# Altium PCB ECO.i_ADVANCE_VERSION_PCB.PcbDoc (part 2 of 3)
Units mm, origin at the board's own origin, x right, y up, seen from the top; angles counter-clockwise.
Board outline 291.08 x 101.6 mm, 4 copper layers (Top Layer, Layer 1, Layer 2, Bottom Layer), stack 1.161 mm thick; 272 components, 228 nets, 849 pads, 240 vias.
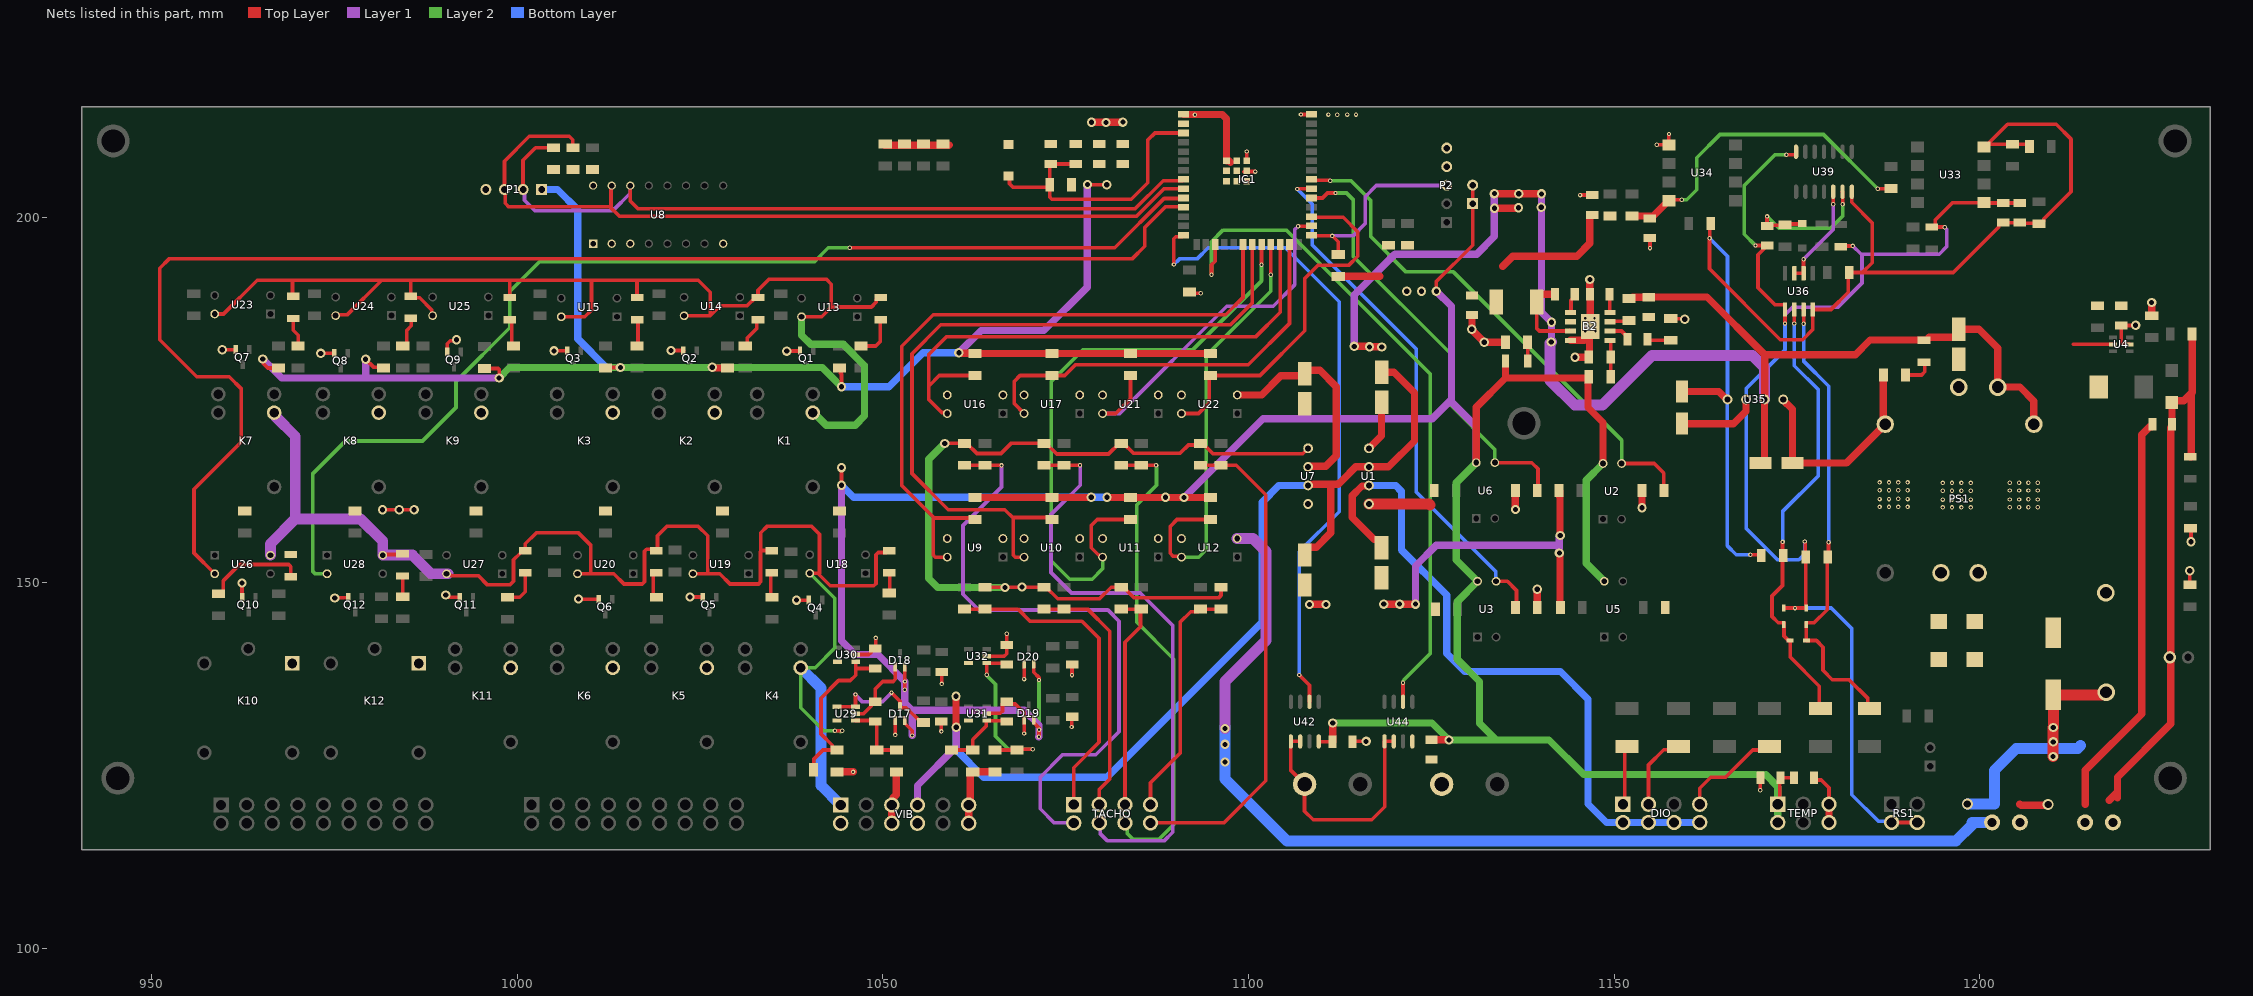
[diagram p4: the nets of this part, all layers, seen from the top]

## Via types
v1: diameter 0.6, hole 0.3, Top Layer to Bottom Layer, 154 vias
v2: diameter 1.27, hole 0.711, Top Layer to Bottom Layer, 80 vias
v3: diameter 2.4, hole 1.6, Top Layer to Bottom Layer, 4 vias
v4: diameter 1.5, hole 1, Top Layer to Bottom Layer, 2 vias

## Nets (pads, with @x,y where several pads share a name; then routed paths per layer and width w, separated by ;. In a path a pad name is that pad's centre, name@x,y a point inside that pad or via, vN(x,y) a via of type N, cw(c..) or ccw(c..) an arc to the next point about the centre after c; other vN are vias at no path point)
+3.3V: C9.2 C12.1 C13.1 C27.1 C28.1 C32.2 C33.2 C35.1 C36.1 D2.POS D17.2 D18.2 D19.2 D20.2 IC1.2 L1.1 P1.1 P4.1 P4.2 R3.2 R4.2 R12.2 R17.1 R18.2 R19.2 R22.1 R23.1 R26.2 R29.2 R30.1 R31.1 R32.2 R43.1 R44.1 R47.2 R48.2 R49.2 R58.1 R59.1 R62.2 R63.2 R64.2 R71.1 R72.2 R73.2 R74.2 R102.1 R103.2 R106.2 R117.2 TEMP.1 TEMP.2 U2.4 U3.4 U5.4 U6.4 U8.16 U34.8 U42.4 U44.4 | length 726.5
  Top Layer w0.5: v2(965.199,180.631) 965.199,180.087 965.894,179.392 R62.2@967.361,179.392 ; v2(979.265,180.602) 980.352,179.515 981.586,179.515 R63.2@981.709,179.392 ; v2(981.583,160.02) v2(983.869,160.02) v2(985.901,160.02) ; R64.2@995.521,179.342 995.529,179.334 997.382,179.334 997.522,179.194 v2(997.522,178.031) ; R32.2@1012.056,179.392 1012.122,179.458 v2(1014.101,179.458) ; R26.2@1044.069,179.392 1044.337,179.125 1044.337,179.09 1044.451,178.976 1044.157,178.681 1044.332,178.505 v2(1044.332,176.82) ; v2(1044.332,163.358) v2(1044.332,165.771) ; v1(1052.981,135.403) 1052.992,135.414 1052.992,136.517 v1(1053.002,136.528) ; D17.2@1052.997,131.191 1052.997,130.826 1054.02,129.804 v1(1054.02,129.136) ; D18.2@1052.997,138.474 1052.997,136.533 v1@1053.008,136.523 ; D19.2@1070.611,131.267 1070.611,130.902 1071.336,130.176 1071.336,129.952 v1(1071.356,129.933) 1071.344,129.921 1071.344,128.987 v1(1071.332,128.975) ; D20.2@1070.611,138.95 1070.611,137.794 1071.346,137.059 v1(1071.346,136.736) ; v2(1077.976,204.47) 1080.58,204.47 v2(1080.601,204.449) ; U42.4@1109.637,128.298 C33.2@1111.449,128.298 ; v2(1125.684,189.891) 1125.684,191.218 1130.646,196.18 P4.1@1130.646,201.86 P4.2@1130.646,204.4 ; U34.8@1157.474,202.272 1157.545,202.343 1157.588,202.3 1157.674,202.386 v1(1159.245,202.386) ; TEMP.1@1172.366,119.747 1172.626,120.007 1172.626,123.259 C36.1@1172.711,123.344 C35.1@1174.608,123.344 ; v1(1186.043,203.911) 1187.836,203.911 R102.1@1187.872,203.947
  Top Layer w1: v2(1026.667,179.488) 1026.74,179.488 1026.836,179.392 R29.2@1028.762,179.392 ; v2(1060.388,181.469) 1060.44,181.418 1062.557,181.418 R43.1@1062.611,181.363 R44.1@1073.117,181.363 R58.1@1083.852,181.363 R59.1@1094.776,181.363 ; R22.1@1062.611,161.678 R23.1@1073.117,161.678 v2@1078.495,161.678 ; v2@1080.654,161.678 R30.1@1083.852,161.678 v2@1091.177,161.678 ; v2(1088.655,161.707) 1088.673,161.689 1091.166,161.689 v2@1091.177,161.678 ; v2(1091.184,161.671) v2@1091.177,161.678 ; R31.1@1094.776,161.678 v2@1091.177,161.678 ; C33.2@1111.449,128.298 C33.2@1111.487,128.26 1111.501,128.273 1111.501,130.824 v2(1111.514,130.837) ; R117.2@1112.266,191.921 1117.957,191.921 1117.981,191.897 ; C32.2@1125.014,128.56 1125.034,128.54 1127.349,128.54 1127.369,128.56 v2(1127.409,128.52) ; U6.4@1131.138,166.448 1131.138,174.027 1135.141,178.03 ; 1134.743,193.288 1136.146,194.691 1144.905,194.691 1146.667,196.453 1146.667,200.284 1146.717,200.334 C28.1@1147.017,200.334 ; D2.POS@1135.141,180.349 1135.141,178.03 ; R12.2@1146.429,178.03 1135.141,178.03 ; R12.2@1146.524,178.192 1146.429,178.098 1146.429,173.99 1148.471,171.948 U2.4@1148.471,166.342 ; R103.2@1152.455,200.184 C27.1@1155.258,200.184 ; C27.1@1154.884,199.854 1155.184,199.854 1155.234,199.904 1155.234,200.067 1157.084,201.917 1157.084,202.01 1157.346,202.272 U34.8@1157.474,202.272
  Layer 1 w1: v2(965.199,180.631) 967.799,178.031 v2(997.522,178.031) ; 979.265,178.181 v2(979.265,180.602) ; v2(1044.332,163.358) 1044.332,142.102 1046.226,140.208 1049.322,140.208 1053.008,136.523 1053.008,135.429 v1(1052.981,135.403) 1052.981,133.58 1053.973,132.588 ; v1(1054.02,129.136) 1054.02,132.541 1053.973,132.588 ; v2(1060.388,181.469) 1063.45,184.531 1072.007,184.531 1077.924,190.448 1077.924,204.418 v2(1077.976,204.47) ; v1(1071.332,128.975) 1071.356,128.999 v1(1071.356,129.933) 1071.356,130.572 1069.34,132.588 1053.973,132.588 ; v2(1091.184,161.671) 1101.979,172.466 1125.12,172.466 1127.583,174.929 ; v2(1125.684,189.891) 1127.76,187.815 1127.76,175.106 1127.583,174.929 ; U6.4@1131.138,166.448 1131.138,171.374 1127.583,174.929
  Layer 2 w0.5: v1(1071.332,128.975) 1071.344,128.987 1071.344,129.921 v1(1071.356,129.933) 1071.351,129.938 1071.351,136.731 v1(1071.346,136.736) ; v1(1159.245,202.386) 1159.904,202.386 1161.288,203.77 1161.288,208.153 1164.463,211.328 1178.626,211.328 v1(1186.043,203.911)
  Layer 2 w1: v2(997.522,178.031) 998.943,179.451 1014.094,179.451 v2(1014.101,179.458) ; v2(1026.667,179.488) 1026.652,179.473 1014.116,179.473 v2(1014.101,179.458) ; v2(1044.332,176.82) 1041.694,179.458 v2(1014.101,179.458) ; v2(1111.514,130.837) 1125.092,130.837 v2(1127.409,128.52) ; v2@1127.413,128.524 1133.861,128.524 ; U6.4@1131.138,166.448 1128.395,163.705 1128.395,153.139 U3.4@1131.311,150.224 1128.522,147.435 1128.522,139.573 1131.575,136.52 1131.575,130.81 1133.861,128.524 ; U2.4@1148.433,166.38 U2.4@1148.471,166.342 1146.175,164.045 1146.175,152.693 U5.4@1148.644,150.224 ; TEMP.2@1172.366,117.248 TEMP.1@1172.366,119.747 1172.366,122.145 1170.712,123.799 1145.82,123.799 1141.095,128.524 1133.861,128.524
  Bottom Layer w1: P1.1@1003.336,203.802 1005.492,203.802 1008.253,201.041 1008.253,183.388 1012.183,179.458 v2(1014.101,179.458) ; v2(1044.332,163.358) 1045.983,161.707 1062.573,161.707 v2(1078.495,161.707) v2(1080.654,161.707) ; v2(1044.332,176.82) 1050.834,176.82 1055.483,181.469 v2(1060.388,181.469)
  other v2: 1121.62,189.891 1123.652,189.891
+5_RS: C26.1 C29.1 C30.1 R101.2 R104.2 R105.1 R108.1 R109.1 R110.1 U33.8 U35.4 U36.8 U39.14 | length 166.2
  Top Layer w0.5: v1@1163.026,197.142 1163.026,192.953 1172.718,183.261 1175.766,183.261 1177.163,184.658 U36.8@1177.163,187.395 1179.646,187.395 1181.989,189.738 1181.989,192.295 R108.1@1182.136,192.442 1183.931,192.442 ; v1(1163.05,197.142) 1163.05,198.842 R105.1@1163.09,198.882 ; v1(1168.626,153.866) 1169.945,153.866 1170.009,153.93 1170.015,153.924 R110.1@1170.09,153.849 ; U39.14@1182.49,203.497 1182.475,203.483 1182.475,202.047 1185.291,199.231 1185.291,193.802 1183.931,192.442 ; U33.8@1200.571,209.629 1200.699,209.629 U33.8@1201.047,209.977 ; R104.2@1206.776,209.677 1206.476,209.977 R101.2@1204.472,209.977 U33.8@1201.047,209.977 ; 1183.931,192.442 1196.377,192.442 1202.598,198.663 1202.598,198.963 1202.898,199.263 C26.1@1203.198,199.263 C29.1@1205.452,199.263 1205.527,199.188 1208.024,199.188 R109.1@1208.099,199.113 1208.399,199.113 1208.749,199.463 1208.749,199.763 1212.469,203.483 1212.469,210.693 1210.437,212.725 1203.795,212.725 U33.8@1201.047,209.977
  Top Layer w1: C30.1@1159.277,176.182 1164.314,176.182 1165.402,175.093 U35.4@1165.497,175.093
  Bottom Layer w0.5: v1@1163.026,197.142 1165.497,194.672 U35.4@1165.497,175.093 1165.479,175.075 1165.479,155.067 1166.68,153.866 v1(1168.626,153.866)
+5V: B2.2 C2.1 C4.1 C6.1 C10.1 C24.1 C31.1 D1.POS D5.POS D6.POS D7.POS D8.POS D9.POS D10.POS D11.POS D12.POS D13.POS D14.POS D15.POS D16.POS K1.2 K2.2 K3.2 K4.2 K5.2 K6.2 K7.2 K8.2 K9.2 K10.A1 K11.2 K12.A1 L2.2 PS1.3 R9.1 R98.2 U1.2 U4.5 U7.2 U13.4 U14.4 U15.4 U18.4 U19.4 U20.4 U23.4 U24.4 U25.4 U26.4 U27.4 U28.4 U29.5 U30.5 U31.5 U32.5 U35.2 VIB.1 VIB.2 VIB.7 VIB.8 | length 724.1
  Top Layer w0.5: U23.4@958.628,186.778 959.827,186.778 964.444,191.395 969.264,191.395 ; D11.POS@969.377,189.183 969.264,189.296 969.264,191.395 ; U24.4@974.884,186.651 976.718,186.651 981.456,191.389 ; U28.4@981.609,153.797 981.697,153.885 984.225,153.885 D16.POS@984.312,153.972 ; U25.4@988.426,186.553 988.301,186.677 988.301,187.338 986.65,188.988 985.651,188.988 D12.POS@985.435,189.204 985.435,191.22 985.387,191.268 ; U27.4@990.339,151.257 990.473,151.123 990.861,151.123 990.982,151.003 994.664,151.003 995.934,149.733 998.982,149.733 999.49,150.241 999.49,153.162 1000.469,154.141 1000.469,154.157 1000.724,154.412 D15.POS@1001.084,154.412 1001.112,154.44 1001.112,155.374 1002.583,156.845 1008.38,156.845 1010.031,155.194 1010.031,151.257 ; D13.POS@998.962,189.033 998.962,191.389 ; U15.4@1006.018,186.403 1009.236,186.403 1010.158,187.325 1010.158,191.262 1010.285,191.389 ; U20.4@1008.246,151.257 1010.031,151.257 ; D7.POS@1016.426,189.033 1016.378,189.081 1016.378,191.389 ; D10.POS@1018.585,154.412 1018.383,154.614 1017.69,154.614 1017.397,154.321 1017.397,150.153 1017.104,149.86 1014.603,149.86 1013.206,151.257 1010.031,151.257 ; D10.POS@1018.994,154.418 1019.175,154.599 1019.175,156.464 1020.445,157.734 1024.763,157.734 1026.033,156.464 1026.033,151.257 ; U14.4@1022.819,186.533 1026.384,186.533 ; U19.4@1024.02,151.257 1026.033,151.257 ; D9.POS@1034.796,154.418 1034.782,154.432 1033.438,154.432 1033.291,154.286 ; U13.4@1038.879,186.403 1041.621,186.403 1042.953,187.735 ; U18.4@1040.005,151.318 1041.285,151.318 ; v1(1043.432,129.794) v1(1044.448,129.794) ; D5.POS@1049.724,189.033 1049.364,189.033 1049.109,188.778 1049.109,188.418 1048.427,187.735 1042.953,187.735 ; D8.POS@1050.715,154.418 1050.46,154.163 1049.348,154.163 1049.055,153.87 1049.055,149.899 1048.762,149.606 1042.797,149.606 1041.285,151.118 1041.285,151.318 ; 1212.768,182.626 1216.057,182.626 U4.5@1218.189,182.626 ; 969.264,191.395 985.26,191.395 985.387,191.268 ; 985.387,191.268 985.266,191.389 998.962,191.389 ; 998.962,191.389 1010.285,191.389 ; 1010.285,191.389 1016.378,191.389 ; 1016.378,191.389 1024.763,191.389 1026.384,189.768 1026.384,186.533 ; 1026.033,151.257 1027.684,151.257 1029.081,149.86 1032.979,149.86 1033.272,150.153 1033.272,154.266 1033.291,154.286 ; 1026.384,186.533 1027.737,187.886 1031.418,187.886 1032.565,189.033 D6.POS@1032.925,189.033 1032.925,190.026 1034.415,191.516 1042.289,191.516 1042.953,190.852 1042.953,187.735 ; 1033.291,154.286 1033.291,156.864 1034.161,157.734 1040.257,157.734 1041.326,156.665 1041.326,151.318 1041.285,151.318
  Top Layer w1: v2(1060.005,134.518) 1060.005,130.292 v2(1060.026,130.271) ; C10.1@1107.449,154.552 1107.449,154.586 1107.749,154.886 1109.291,154.886 1111.25,156.845 1111.25,163.498 ; U7.2@1108.149,163.333 1108.216,163.4 1108.463,163.4 1108.561,163.498 1111.25,163.498 ; 1112.303,163.498 1112.889,164.084 1114.678,165.873 U1.2@1116.463,165.873 1119.135,165.873 1122.68,169.418 1122.68,176.022 1119.895,178.807 1118.481,178.807 1118.181,178.507 C4.1@1118.181,178.384 ; 1112.303,163.613 1112.188,163.498 1111.25,163.498 ; v2(1114.44,182.347) 1116.468,182.347 v2(1116.532,182.282) 1118.175,182.282 v2(1118.201,182.257) ; v2(1133.613,203.236) 1136.922,203.236 v2(1136.935,203.223) 1140.029,203.223 v2(1140.048,203.204) ; v2(1133.641,201.225) 1136.834,201.225 v2(1136.904,201.295) ; R9.1@1152.022,188.891 1152.322,188.891 1152.497,189.066 C6.1@1154.714,189.066 1154.751,189.103 1162.685,189.103 1170.577,181.211 ; C31.1@1169.982,166.389 1170.259,166.389 1170.559,166.689 1170.559,175.075 U35.2@1170.577,175.093 1170.577,181.211 ; PS1.3@1207.383,171.704 1207.383,174.885 1205.484,176.784 v3(1202.436,176.784) 1202.436,182.118 1199.878,184.676 C2.1@1197.102,184.676 1197.102,184.006 1196.677,183.581 1193.097,183.581 1192.727,183.212 D1.POS@1192.367,183.212 1184.988,183.212 1182.987,181.211 1170.577,181.211
  Layer 1 w1: VIB.7@1054.725,119.634 1054.725,122.291 1060.026,127.592 v2(1060.026,130.271) ; v2(1114.44,182.347) 1114.44,189.372 1120.013,194.945 1131.189,194.945 1133.613,197.369 v2(1133.613,203.236) ; v2(1140.048,203.204) 1140.048,187.029 v2(1141.43,185.647) 1141.415,185.631 1141.415,182.964 v2(1141.399,182.949)
  Layer 1 w1.5: U26.4@966.248,153.797 966.248,155.353 969.772,158.877 ; K7.2@966.747,173.284 966.747,173.149 966.997,172.899 966.997,172.701 969.645,170.053 969.645,159.004 969.772,158.877 ; U27.4@990.553,151.257 988.187,151.257 985.647,153.797 U28.4@981.609,153.797 981.609,155.712 978.572,158.75 969.899,158.75 969.772,158.877 ; v2(1141.399,182.949) 1141.227,182.777 1141.227,177.709 1144.607,174.329 1148.419,174.329 1155.192,181.102 1168.908,181.102 1170.577,179.433 U35.2@1170.577,175.093
  Layer 2 w0.5: U18.4@1040.005,151.318 1043.432,147.891 1043.432,141.097 1040.736,138.401 K4.2@1038.771,138.401 1038.771,132.931 1041.908,129.794 v1(1043.432,129.794) 1044.067,129.794 v1@1044.194,129.667
  Layer 2 w1: U13.4@1038.879,186.403 1038.879,183.877 1040.13,182.626 1044.575,182.626 1047.496,179.705 1047.496,172.847 1046.226,171.577 1042.239,171.577 1040.532,173.284 K1.2@1040.411,173.284
  Bottom Layer w1: v2(1060.026,130.271) 1060.026,127.17 1063.752,123.444 1080.643,123.444 1101.852,144.653 1101.852,161.036 1104.149,163.333 U7.2@1108.149,163.333
  Bottom Layer w1.5: K4.2@1038.771,138.401 1041.527,135.645 1041.527,122.332 VIB.1@1044.225,119.634
  other v2: 1140.032,201.377
+5V_DIO: C5.1 R5.2 R6.2 R13.2 R14.2 U1.4 | length 54.9
  Top Layer w1: v2(1118.5,147.102) v2(1120.659,147.102) v2(1122.818,147.102) ; R6.2@1142.47,162.638 1142.57,162.538 1142.57,161.745 1142.591,161.724 v2@1142.591,156.5 ; v2@1142.591,154.087 1142.591,146.694 R14.2@1142.642,146.643
  Top Layer w1.5: U1.4@1116.463,160.793 1124.701,160.793 1124.839,160.655
  Layer 1 w1: v2(1122.818,147.102) 1122.818,152.318 1125.645,155.145 1142.503,155.145 ; v2(1142.503,154.087) 1142.503,155.067 1142.503,156.3 1142.63,156.427 v2(1142.63,156.5)
+5V_FAN: C11.1 R20.1 R21.1 R27.1 R28.1 R41.1 R42.1 R56.1 R57.1 U7.4 | length 120.4
  Top Layer w0.5: v2(1058.462,169.081) R41.1@1061.175,169.081 1061.475,169.081 1062.852,167.704 1066.147,167.704 1067.524,169.081 R42.1@1072.016,169.081 1072.349,169.415 1072.349,169.048 1073.757,167.64 1080.86,167.64 1082.301,169.081 R56.1@1082.601,169.081 1082.901,169.081 1084.252,167.73 1090.639,167.73 1091.78,168.871 1093.219,168.871 R57.1@1093.43,169.081 1093.73,169.081 1095.142,167.669 1107.405,167.669 U7.4@1108.149,168.413 ; R20.1@1063.984,149.423 v2@1066.72,149.423 ; v2(1066.684,149.388) v2@1066.72,149.423 ; v2(1069.025,149.459) v2@1068.99,149.423 ; R28.1@1096.226,149.423 1096.226,148.298 1095.883,147.955 1084.369,147.955 1082.901,149.423 1081.222,149.423 1079.627,147.828 1073.911,147.828 1072.316,149.423 R21.1@1072.016,149.423 v2@1068.99,149.423 ; v2@1066.72,149.423 v2@1068.99,149.423
  Layer 2 w1: v2(1058.462,169.081) 1056.282,166.901 1056.282,150.599 1057.493,149.388 v2(1066.684,149.388)
+12: 12volts.2 C25.1 D21.1 D25.POS P3.1 R99.2 | length 78.5
  Top Layer w1: 1217.678,120.282 1218.577,121.181 ; 1218.819,120.647 1218.819,123.444 1226.116,130.741 1226.116,140.081 1226.116,171.255 1226.285,171.424 1226.285,174.61 D21.1@1226.238,174.657 1226.485,174.905 1227.862,174.905 1228.892,175.935 ; D25.POS@1228.762,167.252 1228.887,167.252 1228.892,167.257 1228.892,175.935 ; R99.2@1229.027,184.019 1229.027,176.07 1228.892,175.935
+48V: C3.1 D3.1 D4.1 PS1.2
  other v1: 1204.087,160.35 1205.365,160.35 1206.643,160.35 1207.921,160.35 1204.087,161.417 1205.365,161.417 1207.921,161.417 1206.643,161.449 1204.087,162.636 1205.365,162.636 1206.643,162.636 1207.921,162.636 1204.087,163.703 1205.365,163.703 1206.643,163.703 1207.921,163.703
  other v3: 1217.242,148.643
AGND: C26.2 C29.2 C30.2 C34.1 D22.NEG D23.NEG R114.2 RS1.2 RS1.4 U33.5 U35.3 U36.5 U37.2 U39.7 U40.1 | length 191
  Top Layer w0.5: v1(1169.323,196.139) 1169.325,196.137 C34.1@1170.446,196.137 ; C34.1@1170.924,196.135 1169.67,194.881 1169.67,190.373 1171.988,188.055 1173.303,188.055 1173.353,188.005 U36.5@1173.353,187.395 1173.354,187.394 1173.354,185.485 v1(1173.356,185.484) ; U37.2@1173.211,146.564 v1(1174.728,146.564) U40.1@1176.245,146.564 1176.24,146.569 1176.24,146.96 1176.192,147.009 1176.192,153.849 1176.117,153.924 1176.117,155.591 1176.069,155.638 v1(1176.069,155.665) ; v1(1173.541,208.562) 1173.553,208.574 1174.826,208.574 1174.87,208.618 U39.7@1174.87,208.965 ; D22.NEG@1180.996,195.996 1181.088,196.088 1181.093,196.083 v1(1182.625,196.083) ; RS1.2@1187.928,117.248 RS1.4@1191.428,117.248 ; D23.NEG@1193.439,198.67 D23.NEG@1193.656,198.67 ; v1(1195.207,198.637) 1195.18,198.637 1195.148,198.67 D23.NEG@1193.656,198.67 ; C29.2@1205.452,201.963 C26.2@1203.198,201.963 1200.617,201.963 U33.5@1200.571,202.009 1196.292,202.009 1193.911,199.628 1193.911,198.925 D23.NEG@1193.656,198.67
  Top Layer w1: C30.2@1159.277,171.782 1166.319,171.782 1168.019,173.482 1168.019,175.075 U35.3@1168.037,175.093
  Layer 1 w0.5: v1(1173.356,185.484) 1173.356,186.693 1174.369,187.706 1180.592,187.706 1183.894,191.008 1183.894,194.814 ; v1(1182.625,196.083) 1183.765,194.943 ; 1183.763,194.945 1194.435,194.945 1195.451,195.961 1195.451,198.367 1195.207,198.61 v1(1195.207,198.637)
  Layer 2 w0.5: v1(1169.323,196.139) 1167.765,197.697 1167.765,204.343 1171.984,208.562 v1@1173.518,208.562
  Bottom Layer w0.5: v1(1173.356,185.484) 1173.356,181.867 1168.037,176.548 U35.3@1168.037,175.093 1168.037,157.462 1172.337,153.162 1175.258,153.162 1176.069,153.973 v1(1176.069,155.665) ; v1(1174.728,146.564) 1179.697,146.564 1182.497,143.764 1182.497,121.031 1186.128,117.4 1187.775,117.4 RS1.2@1187.928,117.248
AIR_CON: DIO.7 F4.1 | length 14.1
  Top Layer w0.5: DIO.7@1161.693,119.747 1161.693,121.944 1163.193,123.444 1165.225,123.444 1168.934,127.153 1170.745,127.153 F4.1@1171.22,127.628
AIR_CON_MCU: IC1.31 R16.2 U6.3 | length 59.6
  Top Layer w0.5: IC1.31@1108.631,202.637 1110.115,202.637 1110.805,203.327 v1(1111.885,203.327) ; U6.3@1133.678,166.448 1138.731,166.448 1139.571,165.608 1139.571,162.719 R16.2@1139.49,162.638
  Layer 2 w0.5: v1(1111.885,203.327) 1113.409,203.327 1114.298,202.438 1114.298,194.691 1127.506,181.483 1127.506,174.421 1133.678,168.25 U6.3@1133.678,166.448
CS: IC1.14 U42.6 | length 89.1
  Top Layer w0.5: v1(1089.787,193.548) 1089.787,197.064 1090.08,197.357 1090.931,197.357 IC1.14@1091.131,197.557 ; v1(1106.932,137.414) 1108.329,136.017 U42.6@1108.329,133.747
  Bottom Layer w0.5: v1(1089.787,193.548) 1090.549,194.31 1092.962,194.31 1094.486,195.834 1105.027,195.834 1112.393,188.468 1112.393,159.749 1106.932,154.288 v1@1106.932,137.581
CS2: IC1.17 U44.6 | length 94
  Top Layer w0.5: v1(1094.94,192.141) 1094.94,193.494 1095.436,193.99 IC1.17@1095.436,196.307 ; v1(1121.123,136.35) 1121.125,136.349 U44.6@1121.125,133.747
  Layer 2 w0.5: v1(1094.94,192.141) 1094.94,196.669 1096.518,198.247 1105.154,198.247 1124.839,178.562 1124.839,140.343 1121.283,136.787 1121.283,136.779 1121.143,136.639 1121.143,136.369 v1(1121.123,136.35)
DGND: C5.2 DIO.2 DIO.4 DIO.6 DIO.8 U1.3 | length 94
  Top Layer w1: U1.3@1116.463,163.333 1116.396,163.266 1115.512,163.266 1114.171,161.925 1114.171,158.955 1117.181,155.945 1117.881,155.945 1118.181,155.645 C5.2@1118.181,154.945
  Bottom Layer w1: U1.3@1116.463,163.333 1120.129,163.333 1120.902,162.56 1120.902,154.559 1127.118,148.343 1127.118,140.342 1129.57,137.89 1142.651,137.89 1146.429,134.112 1146.429,119.761 1148.942,117.248 DIO.2@1151.192,117.248 DIO.4@1154.692,117.248 ; DIO.4@1154.692,117.248 DIO.6@1158.193,117.247 DIO.8@1161.693,117.247
DOOR1_MCU: IC1.32 R8.2 U3.3 | length 72.6
  Top Layer w0.5: v1(1106.658,203.875) 1106.674,203.891 1108.614,203.891 IC1.32@1108.631,203.907 ; U3.3@1133.851,150.224 1135.397,150.224 1136.65,148.971 1136.65,146.803 R8.2@1136.49,146.643
  Bottom Layer w0.5: v1(1106.658,203.875) 1108.71,201.823 1108.71,196.215 1122.934,181.991 1122.934,162.433 1133.793,151.574 1133.793,150.281 U3.3@1133.851,150.224
DOOR_1: DIO.3 F2.1 | length 10.5
  Top Layer w0.5: DIO.3@1154.692,119.747 1154.693,125.104 1156.774,127.185 1158.364,127.185 F2.1@1158.806,127.628
EN: C14.1 C15.1 IC1.3 R71.2 SW1.1 | length 40.4
  Top Layer w0.5: SW1.1@1067.181,205.613 1067.308,205.486 1067.308,204.597 1067.816,204.089 1069.848,204.089 1069.85,204.087 R71.2@1072.458,204.087 ; C14.1@1076.342,207.291 C15.1@1072.933,207.291 1072.808,207.166 R71.2@1072.808,204.461 1072.808,204.437 R71.2@1072.458,204.087 ; IC1.3@1091.131,211.527 1087.192,211.527 1086.231,210.566 1086.231,204.724 1083.973,202.466 1073.101,202.466 1072.808,202.759 1072.808,203.811 1072.532,204.087 R71.2@1072.458,204.087
ENABLE: U36.2 U36.3 U39.12 | length 14
  Top Layer w0.5: U36.3@1174.623,192.335 U36.2@1175.893,192.335 1175.893,194.1 v1@1175.895,194.102 ; U39.12@1179.95,203.497 1179.929,203.477 1179.958,203.449 v1(1179.958,201.796)
  Layer 1 w0.5: v1(1175.896,194.259) 1179.958,198.321 v1(1179.958,201.796)
FAN_1: IC1.20 R22.2 U9.4 | length 94.8
  Top Layer w0.5: 1056.867,158.877 1056.867,153.822 1057.16,153.529 U9.4@1058.801,153.529 ; R22.2@1062.611,158.678 1062.412,158.877 1057.021,158.877 1052.576,163.322 1052.576,182.372 1056.894,186.69 1096.899,186.69 1099.246,189.037 IC1.20@1099.246,196.307
FAN_2: IC1.21 R23.2 U10.4 | length 102.3
  Top Layer w0.5: U10.4@1069.307,153.529 1068.109,153.529 1067.816,153.822 1067.816,158.877 ; R23.2@1073.117,158.678 1072.855,158.94 1067.88,158.94 1067.816,158.877 ; IC1.21@1100.516,196.307 1100.516,188.275 1097.534,185.293 1057.91,185.293 1053.973,181.356 1053.973,164.973 1058.926,160.02 1066.673,160.02 1067.816,158.877
FAN_3: IC1.22 R30.2 U11.4 | length 85
  Top Layer w0.5: U11.4@1080.042,153.529 1079.852,153.529 1079.534,153.847 1079.45,153.847 1078.484,154.813 1078.484,157.861 1079.301,158.678 R30.2@1083.852,158.678 ; v1(1101.765,193.518) 1101.775,193.528 1101.775,196.258 IC1.22@1101.765,196.268
  Layer 2 w0.5: U11.4@1080.042,153.529 1080.042,151.926 1078.611,150.495 1075.563,150.495 1073.023,153.035 1073.023,177.546 1077.341,181.864 1092.327,181.864 1101.765,191.302 v1(1101.765,193.518)
FAN_4: IC1.23 R31.2 U12.4 | length 60.6
  Top Layer w0.5: U12.4@1090.831,153.529 1090.697,153.663 1089.667,153.663 1089.279,154.051 1089.279,157.734 1090.223,158.678 R31.2@1094.776,158.678 ; v1(1103.042,192.131) 1103.049,192.138 1103.049,196.3 IC1.23@1103.056,196.307
  Layer 2 w0.5: U12.4@1090.831,153.529 1093.204,153.529 1094.232,154.557 1094.232,181.102 1103.033,189.903 1103.033,192.123 v1(1103.042,192.131)
FAN_5: IC1.24 R43.2 U16.4 | length 76.2
  Top Layer w0.5: U16.4@1058.801,173.167 1058.667,173.301 1058.034,173.301 1056.259,175.075 1056.259,176.911 ; R43.2@1062.611,178.363 1057.711,178.363 1056.259,176.911 ; IC1.24@1104.326,196.307 1104.326,187.005 1100.963,183.642 1058.672,183.642 1056.259,181.229 1056.259,176.911
FAN_6: IC1.25 R44.2 U17.4 | length 56.7
  Top Layer w0.5: U17.4@1069.307,173.167 1067.943,174.531 1067.943,177.546 1068.76,178.363 R44.2@1073.117,178.363 1074.856,178.363 1076.344,179.851 1099.966,179.851 1105.596,185.481 IC1.25@1105.596,196.307
FAN_7: IC1.28 R58.2 U21.4 | length 51.5
  Top Layer w0.5: U21.4@1080.042,173.167 1081.852,173.167 1083.852,175.167 R58.2@1083.852,178.363 ; v1(1106.781,198.776) 1106.8,198.795 1108.599,198.795 IC1.28@1108.631,198.827
  Layer 1 w0.5: U21.4@1080.042,173.167 1082.36,173.167 1097.026,187.833 1103.376,187.833 1106.297,190.754 1106.297,198.292 v1(1106.781,198.776)
FAN_8: IC1.29 R59.2 U22.4 | length 49.8
  Top Layer w0.5: U22.4@1090.831,173.167 1093.155,173.167 1094.613,174.625 1094.613,178.2 R59.2@1094.776,178.363 1101.574,178.363 1107.694,184.483 1107.694,191.643 1109.472,193.421 1113.663,193.421 1114.933,194.691 1114.933,197.993 1112.935,199.991 1108.736,199.991 IC1.29@1108.631,200.097
FAN_RELAY1: IC1.10 U28.2 | length 155.1
  Top Layer w0.5: v1(1045.464,195.834) 1081.721,195.834 1088.452,202.565 1091.059,202.565 IC1.10@1091.131,202.637
  Layer 2 w0.5: U28.2@973.989,151.257 972.351,151.257 972.058,151.55 972.058,164.973 976.503,169.418 987.044,169.418 991.616,173.99 991.616,177.546 998.982,184.912 998.982,189.865 1003.046,193.929 1040.638,193.929 1042.543,195.834 v1(1045.464,195.834)
FAN_RELAY2: IC1.11 U26.2 | length 197.9
  Top Layer w0.5: U26.2@958.628,151.257 955.802,154.083 955.802,162.814 962.279,169.291 962.279,176.53 960.628,178.181 956.183,178.181 951.103,183.261 951.103,193.04 952.373,194.31 1084.072,194.31 1085.795,196.033 1085.795,198.605 1088.612,201.422 1091.075,201.422 IC1.11@1091.131,201.367
FAN_T1: R20.2 R24.2 TACHO.1 | length 44.2
  Top Layer w0.5: R24.2@1061.175,146.423 R20.2@1063.984,146.423 1068.459,146.423 1070.103,144.779 1077.215,144.779 1079.557,142.437 1079.557,128.2 1076.095,124.738 TACHO.1@1076.095,119.687
FAN_T2: R21.2 R25.2 TACHO.3 | length 34.6
  Top Layer w0.5: R21.2@1072.016,146.423 R25.2@1074.752,146.423 1077.984,146.423 1081.024,143.383 1081.024,123.19 1079.595,121.761 TACHO.3@1079.595,119.687
FAN_T3: R27.2 R33.2 TACHO.5 | length 30.4
  Top Layer w0.5: R27.2@1082.601,146.423 R33.2@1085.337,146.423 1085.215,146.301 1085.215,144.018 1083.096,141.899 TACHO.5@1083.095,119.687
FAN_T4: R28.2 R34.2 TACHO.7 | length 32.9
  Top Layer w0.5: TACHO.7@1086.596,119.687 1086.596,122.666 1090.676,126.746 1090.676,144.653 1092.096,146.073 1093.08,146.073 R34.2@1093.43,146.423 R28.2@1096.226,146.423
FAN_T5: R41.2 R45.2 TACHO.2 | length 85.9
  Top Layer w0.5: R41.2@1061.175,166.081 R45.2@1063.984,166.081 1066.2,166.081 v1@1066.223,166.058
  Layer 1 w0.5: v1@1066.223,166.058 1066.223,163.126 1060.958,157.861 1060.958,148.463 1063.117,146.304 1080.77,146.304 1082.294,144.78 1082.294,129.667 1079.119,126.492 1074.547,126.492 1071.499,123.444 1071.499,119.126 1073.438,117.187 TACHO.2@1076.095,117.187
  other v1: 1066.211,166.07
FAN_T6: R42.2 R46.2 TACHO.4 | length 81.6
  Top Layer w0.5: R42.2@1072.016,166.081 R46.2@1074.752,166.081 v1(1076.95,166.081) v1@1076.992,166.123
  Layer 1 w0.5: v1@1076.992,166.123 1076.992,163.354 1072.993,159.355 1072.993,151.414 1075.786,148.621 1085.184,148.621 1089.632,144.173 1089.632,115.924 1088.433,114.725 1080.726,114.725 1079.702,115.749 1079.702,117.081 TACHO.4@1079.595,117.188
FAN_T7: R56.2 R60.2 TACHO.6 | length 66.3
  Top Layer w0.5: R56.2@1082.601,166.081 R60.2@1085.337,166.081 v1(1087.359,166.081) v1@1087.406,166.035
  Layer 2 w0.5: TACHO.6@1083.095,117.187 1083.402,116.881 1083.402,115.732 1084.199,114.935 1087.755,114.935 1089.787,116.967 1089.787,139.573 1084.707,144.653 1084.707,160.655 1087.406,163.354 v1@1087.406,166.035
FAN_T8: R57.2 R61.2 TACHO.8 | length 67.9
  Top Layer w0.5: TACHO.8@1086.596,117.187 1096.611,117.187 1102.36,122.936 1102.36,162.052 1098.331,166.081 R61.2@1096.226,166.081 R57.2@1093.43,166.081
FGND: C3.2 C11.2 POWER.1 PS1.1 U7.3 U9.2 U10.2 U11.2 U12.2 U16.2 U17.2 U21.2 U22.2 | length 214.8
  Top Layer w1: U22.2@1098.451,175.707 1101.791,175.707 1104.399,178.315 1107.149,178.315 1107.449,178.615 1107.449,179.084 1109.763,179.084 1112.012,176.835 1112.012,167.386 1110.566,165.94 1108.216,165.94 U7.3@1108.149,165.873
  Top Layer w1.5: v2(1210.022,126.258) 1210.03,126.265 v2(1210.03,128.268) 1210.034,128.272 v2(1210.034,130.231) ; v2@1210.056,130.231 C3.2@1210.056,133.838 ; C3.2@1210.056,134.688 1216.662,134.688 1217.012,135.039 v3(1217.256,135.039)
  Layer 1 w1.5: v2(1096.783,130.084) 1096.783,136.536 1102.36,142.113 1102.36,154.305 1100.596,156.069 U12.2@1098.451,156.069
  Bottom Layer w1.5: v2@1096.772,125.512 1096.772,123.19 1105.242,114.72 1196.709,114.72 1198.907,116.918 1198.907,117.248 POWER.1@1201.971,117.248 ; v2@1096.772,130.084 v2@1096.772,130.302 ; v2(1096.783,125.512) v2(1096.783,127.925) v2(1096.783,130.084) ; v4(1198.296,119.775) 1201.943,119.775 1201.971,119.747 1201.971,124.376 1204.976,127.381 1213.387,127.381 1213.747,127.74
FLOOD_SENSOR_NO: DIO.1 F1.1 | length 8.1
  Top Layer w0.5: DIO.1@1151.192,119.747 1151.443,119.998 1151.443,127.334 F1.1@1151.737,127.628
FLOOD_SENSOR_SIG: IC1.33 R7.2 U2.3 | length 72
  Top Layer w0.5: IC1.33@1108.631,205.177 1108.764,205.043 1111.098,205.043 1111.132,205.009 v1(1111.159,205.009) ; U2.3@1151.011,166.342 1155.474,166.342 1156.793,165.023 R7.2@1156.793,162.638
  Layer 2 w0.5: v1(1111.159,205.009) 1114.013,205.009 1116.711,202.311 1116.711,197.358 1121.537,192.532 1128.014,192.532 1151.011,169.535 U2.3@1151.011,166.342
GND: 12volts.1 B2.4 B2.9 C2.2 C4.2 C6.2 C7.2 C9.1 C10.2 C12.2 C13.2 C14.2 C15.2 C16.2 C17.2 C18.2 C19.2 C20.2 C21.2 C22.2 C23.2 C24.2 C25.2 C27.2 C28.2 C31.2 C32.1 C33.1 C35.2 C36.2 D17.1 D18.1 D19.1 D20.1 IC1.1 IC1.40 IC1.41 IC1.42 IC1.43 IC1.44 IC1.45 IC1.46 IC1.47 IC1.48 IC1.49 P1.4 P2.4 P2.5 PS1.5 Q1.2 Q2.2 Q3.2 Q4.2 Q5.2 Q6.2 Q7.2 Q8.2 Q9.2 Q10.2 Q11.2 Q12.2 R1.2 R2.2 R7.1 R8.1 R10.1 R11.1 R15.1 R16.1 R85.1 R86.1 R88.1 R92.1 R93.2 R94.1 R95.1 R96.1 R97.1 R100.1 R115.1 R116.2 SW1.2 TEMP.5 TEMP.6 U1.1 U4.2 U7.1 U8.1 U8.2 U8.3 U8.8 U9.3 U10.3 U11.3 U12.3 U16.3 U17.3 U21.3 U22.3 U29.2 U30.2 U31.2 U32.2 U34.5 U35.1 U41.1 U42.1 U42.2 U43.1 U44.1 U44.2 VIB.5 VIB.6 VIB.11 VIB.12 | length 309
  Top Layer w0.5: v2(959.653,181.895) 961.495,181.895 961.52,181.921 Q7.2@961.523,181.917 ; v2(962.366,150.005) 962.366,148.056 Q10.2@962.377,148.045 ; v2(973.119,181.391) 973.14,181.411 974.942,181.411 Q8.2@974.962,181.432 ; v2@974.852,148.082 974.979,147.955 v2(975.042,147.955) 976.818,147.955 Q12.2@976.908,148.045 ; v2(990.228,148.338) 990.437,148.338 990.729,148.045 Q11.2@992.119,148.045 ; Q9.2@990.436,181.579 990.436,182.716 990.826,183.106 991.56,183.106 v2(991.707,183.254) ; v2(1005.02,181.733) 1005.033,181.746 Q3.2@1006.83,181.746 ; v2(1008.382,147.794) 1008.392,147.784 1011.13,147.784 Q6.2@1011.141,147.773 ; v2@1020.826,181.737 1020.865,181.776 v2(1021.018,181.776) 1022.689,181.776 1022.728,181.737 Q2.2@1022.729,181.738 ; v2@1023.366,147.955 1023.493,148.082 v2(1023.62,148.082) 1025.156,148.082 1025.283,147.955 Q5.2@1025.374,148.045 ; v2(1036.851,181.696) 1036.872,181.717 1038.643,181.717 Q1.2@1038.664,181.738 ; v2(1038.175,147.652) v2@1038.303,147.652 ; v2@1038.352,147.701 v2@1038.303,147.652 ; Q4.2@1039.888,147.662 1039.879,147.652 v2@1038.303,147.652 ; U29.2@1046.246,132.131 1047.351,132.131 1048.375,133.155 1048.375,133.455 1048.675,133.755 C19.2@1048.975,133.755 1048.975,135.549 1049.041,135.615 1049.056,135.615 1049.966,136.525 1051.404,136.525 1051.697,136.818 D18.1@1051.697,138.474 ; U30.2@1046.285,140.178 1046.314,140.208 1048.083,140.208 1048.375,140.501 1048.375,140.72 1048.675,141.02 C18.2@1048.975,141.02 ; C18.2@1049.01,141.055 1049.024,141.068 v1(1049.024,142.484) ; v1(1051.688,129.222) 1051.697,129.232 D17.1@1051.697,131.191 ; C17.2@1057.985,131.055 1057.993,131.047 v1(1057.993,129.695) ; v1(1058.049,136.198) 1058.049,137.813 1058.065,137.829 C16.2@1058.051,137.844 ; U31.2@1064.201,132.131 1064.246,132.176 1066.06,132.176 1066.353,132.469 1066.353,133.455 1066.653,133.755 C20.2@1066.953,133.755 1067.253,133.455 1068.092,133.455 1069.311,132.236 D19.1@1069.311,131.267 ; U32.2@1064.201,139.995 1066.587,139.995 1066.927,140.335 1066.927,141.502 C23.2@1066.953,141.528 1066.941,141.54 v1(1066.941,143.056) ; D19.1@1069.311,131.258 1069.311,130.773 1069.314,130.77 v1(1069.314,129.413) ; v1(1069.311,136.853) D20.1@1069.311,138.95 ; v1(1075.809,130.305) 1075.809,131.651 C22.2@1075.864,131.705 ; v1(1075.863,137.395) C21.2@1075.864,138.828 ; IC1.1@1091.302,214.025 1092.656,214.025 v1(1092.659,214.023) v1@1092.661,214.021 ; R93.2@1091.909,189.78 1092.059,189.63 1093.451,189.63 v1(1093.47,189.611) ; IC1.48@1099.355,206.248 1099.781,206.248 1099.797,206.264 1100.893,206.264 v1(1100.912,206.245) ; v1@1099.747,208.896 v1@1099.76,208.908 ; v1(1099.76,208.997) v1@1099.76,208.908 ; IC1.49@1099.781,207.747 1099.76,207.768 v1@1099.76,208.908 ; U42.2@1107.059,128.337 U42.1@1105.789,128.337 1105.789,124.347 U41.1@1107.66,122.476 1107.66,118.779 1108.837,117.602 1116.838,117.602 1118.616,119.38 1118.616,127.566 1118.598,127.584 1118.598,128.324 U44.1@1118.585,128.337 U44.2@1119.855,128.337 ; v1@1107.149,214.062 v1(1107.151,214.059) 1107.154,214.057 IC1.40@1108.508,214.057 ; C33.1@1114.187,128.26 1114.286,128.359 1114.31,128.335 v2(1116.079,128.335) ; U43.1@1126.363,122.44 U43.1@1126.399,122.477 ; v1(1145.344,203.04) 1146.801,203.04 1146.906,203.145 C28.2@1147.017,203.034 ; C27.2@1154.884,197.154 1154.905,197.133 1154.886,197.115 1154.9,197.101 v1(1154.9,195.78) ; v1(1155.812,209.918) 1157.334,209.918 1157.366,209.885 1157.423,209.943 U34.5@1157.474,209.892 1157.474,211.324 v1@1157.478,211.328 ; R11.1@1157.737,186.179 1157.804,186.113 1159.578,186.113 v2(1159.644,186.046) ; v1(1169.972,121.655) 1169.991,121.674 1169.991,123.325 C36.2@1170.011,123.344 ; C35.2@1177.308,123.344 1177.317,123.344 1177.608,123.054 1178.315,123.054 1179.366,122.003 TEMP.5@1179.366,119.747 ; U4.2@1220.487,182.626 1219.631,182.626 1219.338,182.919 C24.2@1219.338,185.205 1221.025,185.205 v2@1221.035,185.195 ; v2(1228.714,151.668) 1228.714,149.76 R116.2@1228.727,149.747 ; R115.1@1228.797,157.49 1228.882,157.404 v2(1228.882,155.624)
  Top Layer w1: R86.1@1043.71,124.163 v1(1045.929,124.163) ; R96.1@1050.217,209.831 1053.505,209.831 1055.538,209.831 1055.872,209.831 1059.04,209.831 R95.1@1059.088,209.879 ; VIB.5@1051.225,119.634 1051.436,119.844 1051.436,120.622 1051.844,121.03 R85.1@1051.844,124.163 ; VIB.6@1051.225,117.134 VIB.5@1051.225,119.634 ; VIB.12@1061.725,117.134 VIB.11@1061.725,119.634 1061.936,119.844 1061.936,124.063 1062.036,124.163 R88.1@1062.281,124.163 R92.1@1065.319,124.163 ; SW1.2@1067.106,210.058 SW1.2@1067.181,209.983 SW1.2@1067.116,209.983 ; v2(1078.521,212.988) 1078.528,212.981 1080.494,212.981 v2(1080.501,212.974) 1080.542,213.015 v2(1082.813,213.015) ; IC1.1@1091.131,214.067 1096.395,214.067 1096.981,213.481 IC1.43@1096.981,207.747 ; IC1.43@1097.28,207.772 1097.534,207.518 ; v2(1108.329,147.066) 1110.58,147.066 v2(1110.589,147.057) ; U1.1@1116.463,168.413 1118.181,170.131 C4.2@1118.181,174.684 ; v2(1130.51,184.684) 1130.554,184.64 C9.1@1130.554,186.61 ; v2@1130.736,184.396 v2@1132.214,182.919 ; v2(1132.216,182.916) v2@1132.214,182.919 ; R2.2@1135.151,182.919 v2@1132.214,182.919 ; v2(1136.49,160.053) R16.1@1136.49,162.638 ; R8.1@1139.49,146.643 v2(1139.49,149.144) ; B2.4@1144.018,183.174 1145.897,183.174 1146.047,183.324 1146.365,183.324 B2.9@1146.624,183.583 ; v2(1144.65,180.852) 1146.48,180.852 1146.484,180.848 R10.1@1146.524,180.888 1146.624,180.988 B2.9@1146.624,183.583 ; B2.9@1146.095,185.714 B2.9@1146.73,185.079 ; v2(1146.674,191.507) C7.2@1146.674,189.465 1146.674,189.165 1146.73,189.109 B2.9@1146.73,185.079 ; R7.1@1153.793,162.638 1153.793,160.276 v2(1153.795,160.274) ; U35.1@1173.117,175.093 1173.117,174.999 1174.382,173.734 C31.2@1174.382,166.389 1181.748,166.389 PS1.5@1187.063,171.704 1187.063,172.083 1186.783,172.363 1186.783,178.379 R1.2@1186.839,178.435 ; TEMP.6@1179.366,117.247 TEMP.5@1179.366,119.747 ; 1214.42,119.747 1214.42,124.382 1222.121,132.083 1222.121,170.26 1223.235,171.374 1223.535,171.374 1223.585,171.424 C25.2@1223.585,171.724 ; v2(1223.491,188.342) 1223.491,186.653 1223.546,186.598 R100.1@1223.497,186.549 ; B2.9@1146.624,183.583 1146.73,183.689 B2.9@1146.73,185.079
  other v1: 1194.919,160.325 1196.197,160.325 1197.475,160.325 1198.753,160.325 1186.291,160.401 1187.569,160.401 1188.847,160.401 1190.125,160.401 1194.919,161.392 1196.197,161.392 1198.753,161.392 1197.475,161.424 1186.291,161.468 1187.569,161.468 1190.125,161.468 1188.847,161.5 1194.919,162.611 1196.197,162.611 1197.475,162.611 1198.753,162.611 1186.291,162.687 1187.569,162.687 1188.847,162.687 1190.125,162.687 1194.919,163.678 1196.197,163.678 1197.475,163.678 1198.753,163.678 1186.291,163.754 1187.569,163.754 1188.847,163.754 1190.125,163.754 1146.048,184.404 1147.445,184.404 1146.048,186.182 1147.318,186.182 1157.486,211.385 1110.917,214.04 1112.135,214.034 1113.495,214.048 1114.687,214.045
  other v2: 1221.299,185.24
  other v3: 1197.102,176.784
IO_0: IC1.27 P2.3 R117.1 | length 26.8
  Top Layer w0.5: IC1.27@1108.631,197.557 1108.713,197.475 1111.434,197.475 1112.266,196.643 R117.1@1112.266,194.921
  Layer 1 w0.5: v1(1111.453,197.456) 1114.269,197.456 1115.949,199.136 1115.949,202.819 1117.473,204.343 P2.3@1127.489,204.343
IO_SCL: IC1.8 P1.2 R18.1 U8.14 | length 107.4
  Top Layer w0.5: P1.2@1000.796,203.802 1000.796,207.808 1002.508,209.52 R18.1@1004.97,209.52 ; U8.14@1015.457,204.332 1015.457,202.219 1016.508,201.168 1084.482,201.168 1088.32,205.007 1090.96,205.007 IC1.8@1091.131,205.177
  Layer 1 w0.5: P1.2@1000.796,203.802 1000.987,203.611 1000.987,202.338 1002.411,200.914 1013.079,200.914 1015.457,203.292 U8.14@1015.457,204.332
IO_SDA: IC1.9 P1.3 R19.1 U8.15 | length 115.9
  Top Layer w0.5: R19.1@1007.607,209.52 1007.607,210.585 1007.118,211.074 1001.649,211.074 998.256,207.681 P1.3@998.256,203.802 998.347,203.711 998.347,201.93 998.855,201.422 1012.698,201.422 ; U8.15@1012.917,204.332 1012.825,204.24 1012.825,201.549 1012.698,201.422 ; IC1.9@1091.131,203.907 1088.447,203.907 1084.692,200.152 1013.968,200.152 1012.698,201.422
NETA: F5.1 R110.2 U36.6 U37.1 U38.2 | length 62.6
  Top Layer w0.5: v1(1173.025,155.614) 1173.025,155.604 1173.02,155.599 1173.02,153.929 1173.015,153.924 1173.015,149.649 1171.575,148.209 1171.575,145.415 1172.418,144.572 1173.206,144.572 1173.211,144.567 U37.1@1173.211,144.329 1173.211,142.744 1173.821,142.134 1174.054,142.134 1174.059,142.129 1174.059,139.883 1178.052,135.89 1178.052,133.042 F5.1@1178.237,132.858 F5.1@1178.922,132.858 ; v1(1174.614,185.484) 1174.619,185.488 1174.619,187.391 U36.6@1174.623,187.395
  Bottom Layer w0.5: v1@1173.026,155.615 1173.026,159.766 1177.925,164.665 1177.925,176.403 1174.614,179.714 v1(1174.614,185.484)
NETB: F6.1 R114.1 U36.7 U38.1 U40.2 | length 63.5
  Top Layer w0.5: U36.7@1175.893,187.395 1175.896,187.392 v1(1175.896,185.454) ; U38.1@1176.245,142.139 U40.2@1176.245,144.329 1176.245,144.567 1176.25,144.572 1177.336,144.572 1179.117,146.353 R114.1@1179.117,153.924 ; U38.1@1176.294,142.134 1177.65,142.134 1178.56,141.224 1178.56,138.049 1179.83,136.779 1182.116,136.779 1184.69,134.205 1184.69,133.058 F6.1@1184.89,132.858 ; R114.1@1179.312,153.885 1179.312,155.565 v1(1179.322,155.575)
  Bottom Layer w0.5: v1(1175.896,185.454) 1175.896,180.337 1179.322,176.911 v1(1179.322,155.575)
NetB2_1: B2.1 C1.1 | length 2.7
  Top Layer w0.5: B2.1@1144.018,186.984 1144.09,187.056 1144.09,188.653 1144.602,189.165 C1.1@1144.602,189.465
NetB2_3: B2.3 C1.2 L1.2 | length 12
  Top Layer w0.5: L1.2@1139.426,188.393 1139.426,184.803 1139.785,184.444 B2.3@1144.018,184.444 B2.3@1143.918,184.544 ; C1.2@1141.73,189.293 C1.2@1141.902,189.465
  Top Layer w1: L1.2@1139.426,188.393 1139.426,189.04 1139.851,189.465 C1.2@1141.902,189.465
NetB2_5: B2.5 R10.2 R12.1 | length 5
  Top Layer w0.5: B2.5@1149.442,183.174 1149.524,183.092 1149.524,181.229 R12.1@1149.524,178.192
NetB2_6: B2.6 C8.1 | length 3
  Top Layer w0.5: B2.6@1149.442,184.444 1150.99,184.444 1151.83,183.604 C8.1@1151.83,183.304
NetB2_7: B2.7 R9.2 | length 2.7
  Top Layer w0.5: B2.7@1149.442,185.714 1149.53,185.802 1151.934,185.802 R9.2@1152.022,185.891
NetB2_8: B2.8 C7.1 | length 2.5
  Top Layer w0.5: C7.1@1149.374,189.465 1149.374,187.052 B2.8@1149.442,186.984
NetC8_2: C8.2 R11.2 | length 3.3
  Top Layer w0.5: C8.2@1154.53,183.304 1154.655,183.179 R11.2@1157.737,183.179
NetC18_1: C18.1 R82.2 R86.2 U30.1 | length 23.6
  Top Layer w0.5: R82.2@1040.523,124.463 1040.523,125.869 1041.817,127.163 R86.2@1043.41,127.163 ; R86.2@1043.71,127.163 R86.2@1043.41,127.163 ; U30.1@1046.285,139.228 1046.285,138.306 ; C18.1@1048.975,138.32 1048.962,138.306 1046.285,138.306 ; R86.2@1043.41,127.163 1043.06,127.513 1043.06,127.813 1041.527,129.345 1041.527,134.239 1043.94,136.652 1045.552,136.652 1046.285,137.384 1046.285,138.306
NetC19_1: C19.1 R81.1 R85.2 U29.1 | length 9.4
  Top Layer w0.5: U29.1@1046.246,131.181 1048.849,131.181 C19.1@1048.975,131.055 1049.15,130.88 R81.1@1049.15,127.163 R85.2@1051.844,127.163
NetC20_1: C20.1 R87.2 R88.2 U31.1 | length 10.5
  Top Layer w0.5: R87.2@1059.39,127.163 R88.2@1062.281,127.163 1062.281,128.577 1064.133,130.429 1064.133,131.136 1064.178,131.181 U31.1@1064.201,131.181 1064.246,131.136 1066.872,131.136 C20.1@1066.953,131.055
NetC23_1: C23.1 R89.2 R92.2 U32.1 | length 24.2
  Top Layer w0.5: v1(1064.193,137.45) 1064.201,137.457 U32.1@1064.201,139.045 1064.246,139 1066.782,139 C23.1@1066.953,138.828 ; R92.2@1065.319,127.163 R89.2@1068.322,127.163 1068.413,127.254 v1(1070.483,127.254)
  Layer 2 w0.5: v1@1064.26,137.289 1065.403,136.145 1065.403,129.032 1067.181,127.254 v1(1070.483,127.254)
NetC34_2: C34.2 D24.2 R113.2 U39.13 | length 21.3
  Top Layer w0.5: v1(1170.912,200.12) 1170.9,200.108 1170.9,198.859 C34.2@1170.924,198.835 1170.999,198.91 1173.278,198.91 R113.2@1173.353,198.985 1173.449,199.081 1175.628,199.081 D24.2@1175.725,199.177 ; U39.13@1181.22,203.497 1181.232,203.485 v1(1181.232,201.793)
  Layer 2 w0.5: v1(1170.912,200.12) 1172.532,198.501 1179.576,198.501 1181.232,200.157 v1(1181.232,201.793)
NetD1_NEG: D1.NEG R1.1 | length 4.2
  Top Layer w0.5: R1.1@1189.839,178.435 1192.022,178.435 1192.45,178.863 1192.45,180.109 D1.NEG@1192.367,180.192
NetD2_NEG: D2.NEG R2.1 | length 2.6
  Top Layer w0.5: R2.1@1138.151,182.919 1138.156,182.914 1138.156,180.354 D2.NEG@1138.161,180.349
NetD3_2: D3.2 D4.2 POWER.2 | length 4
  Top Layer w1: 1205.472,119.747 1205.616,119.603 1209.232,119.603 v4(1209.333,119.704)
NetD5_NEG: D5.NEG R35.2 | length 5.9
  Top Layer w0.5: R35.2@1047.001,182.392 1049.04,182.392 1049.655,183.007 1049.655,185.944 D5.NEG@1049.724,186.013
NetD6_NEG: D6.NEG R36.2 | length 4.3
  Top Layer w0.5: R36.2@1031.175,182.392 1031.428,182.645 1031.428,183.449 1032.764,184.785 1032.764,185.852 D6.NEG@1032.925,186.013
NetD7_NEG: D7.NEG R38.2 | length 3.7
  Top Layer w0.5: D7.NEG@1016.426,186.013 1016.508,185.931 R38.2@1016.508,182.392
NetD8_NEG: D8.NEG R50.2 | length 2.8
  Top Layer w0.5: R50.2@1050.878,148.622 1050.925,148.669 1050.925,151.351 D8.NEG@1050.878,151.398
NetD9_NEG: D9.NEG R51.2 | length 3.5
  Top Layer w0.5: D9.NEG@1034.796,151.398 1034.669,151.271 1034.669,148.197 R51.2@1034.831,148.035
NetD10_NEG: D10.NEG R53.2 | length 3.4
  Top Layer w0.5: D10.NEG@1018.585,151.392 1018.62,151.357 R53.2@1018.62,148.035
NetD11_NEG: D11.NEG R65.2 | length 4
  Top Layer w0.5: D11.NEG@969.377,186.163 969.377,184.545 970.037,183.885 R65.2@970.037,182.392
NetD12_NEG: D12.NEG R66.2 | length 4.4
  Top Layer w0.5: R66.2@984.354,182.392 984.535,182.392 984.885,182.742 984.885,184.531 985.52,185.166 985.52,186.1 D12.NEG@985.435,186.184
NetD13_NEG: D13.NEG R69.2 | length 3.9
  Top Layer w0.5: D13.NEG@998.962,186.013 998.981,186.013 999.236,185.758 999.236,182.645 R69.2@999.488,182.392
NetD14_NEG: D14.NEG R75.2 | length 13.9
  Top Layer w0.5: R75.2@959.168,148.52 959.468,148.52 959.818,148.87 959.818,150.32 962.025,152.527 968.732,152.527 969.025,152.234 D14.NEG@969.025,150.867
NetD15_NEG: D15.NEG R77.2 | length 5.3
  Top Layer w0.5: R77.2@998.665,148.035 1000.332,148.035 1001.084,148.787 D15.NEG@1001.084,151.392
NetD16_NEG: D16.NEG R78.2 | length 2.9
  Top Layer w0.5: D16.NEG@984.312,150.952 984.347,150.917 R78.2@984.347,148.114
NetD17_3: D17.3 R83.1 U29.3 U29.4 | length 16.7
  Top Layer w0.5: U29.4@1043.736,133.081 U29.3@1046.246,133.081 v1(1046.246,134.747) ; v1(1051.179,135.001) 1052.347,133.833 1052.347,132.947 1053.189,132.947 1055.231,130.905 R83.1@1055.531,130.905
  Layer 1 w0.5: v1@1046.193,134.749 1047.211,133.731 1049.909,133.731 v1(1051.179,135.001)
